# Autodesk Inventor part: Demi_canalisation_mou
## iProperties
Shininess: 64.0
Length Units: 11269
Angle Units: 11279
Time Units: 11290
Mass Units: 11283
Length Display Precision: 3
Angle Display Precision: 2
Compacted: True
Part Number: Demi_canalisation_mou
Document SubType Name: Sheet Metal
Created: 2008-02
Material: Acier inoxydable, austénitique
Designer: Pascal
Density: 0.0
Volumn: 0.0
Area: 0.0
PropertySet Name: Model Information
Control State: 0
Master: False
Checked Out: False
Author: Pascal
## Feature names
1. Plaque1
2. Pli1
3. Plaque2
4. Pli2
5. Plaque3
6. Pli3
7. Ouverture1
